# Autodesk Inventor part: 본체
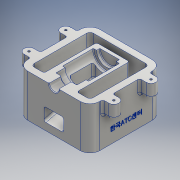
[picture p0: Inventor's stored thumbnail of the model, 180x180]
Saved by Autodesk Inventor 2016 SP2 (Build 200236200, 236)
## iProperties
Created: 2018-01
Part Number: 본체
Material: 알루미늄 6061
Document SubType Name: Modeling
Designer: Administrator
Density: 2.7 g/cm^3
Appearance: 알루미늄 - 평지
Mass: 988.682 g
Surface Area: 837.246 cm^2
Volume: 366.178 cm^3
Author: Administrator
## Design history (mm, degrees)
sketch "스케치1"
  geometry: L1 (-40, 55)-(40, 55); L2 (55, 40)-(55, -40); L3 (40, -55)-(-40, -55); L4 (-55, -40)-(-55, 40); L5 (-55, 55)-(55, -55); L6 (55, 55)-(-55, -55); L7 (40, 45)-(-40, 45); L8 (-45, 40)-(-45, -40); L9 (-40, -45)-(40, -45); L10 (45, -40)-(45, 40); A1 r 15 centre (-40, 40) between (-40, 55) and (-55, 40); A2 r 15 centre (40, 40) between (55, 40) and (40, 55); A3 r 15 centre (40, -40) between (40, -55) and (55, -40); A4 r 15 centre (-40, -40) between (-55, -40) and (-40, -55); A5 r 5 centre (-40, 40) between (-40, 45) and (-45, 40); A6 r 5 centre (40, 40) between (45, 40) and (40, 45); A7 r 5 centre (40, -40) between (40, -45) and (45, -40); A8 r 5 centre (-40, -40) between (-45, -40) and (-40, -45); 1 further point
  constraints: 20 end point, 16 point on circle, 16 tangent, 8 centre point, 8 point on line, 6 equal radius, 4 parallel, 2 midpoint, 2 perpendicular, 1 horizontal, 3 other
  dimensions: "d0" = 110 distance of L5.end L6.end; "d1" = 110 distance of L6.start L5.end; "d2" = 10 distance between parallel lines of L1 L7; "d3" = 15 radius of A1; "d4" = 5 radius of A5
extrude "돌출1" new body sketch "스케치1" distance "d5" = 65; taper "d6" = 0 deg
sketch "스케치2"
  geometry: L1 (-40, -55)-(40, -55) reference; L2 (-55, 40)-(-55, -40) reference; L3 (55, -40)-(55, 40) reference; L4 (-65, 35.5)-(-48.474, 35.5); L5 (-65, 20.5)-(-48.474, 20.5); L6 (-65, -20.5)-(-48.474, -20.5); L7 (-48.474, -20.5)-(-48.474, -35.5); L8 (-48.474, -35.5)-(-65, -35.5); L9 (64.286, -20.5)-(47.99, -20.5); L10 (47.99, -20.5)-(47.99, -35.5); L11 (47.99, -35.5)-(64.286, -35.5); L12 (65, 20.5)-(47.99, 20.5); L13 (47.99, 20.5)-(47.99, 35.5); L14 (47.99, 35.5)-(65, 35.5); L15 (-48.474, 20.5)-(-48.474, 35.5); A1 r 7.5 centre (-65, 28) between (-65, 35.5) and (-65, 20.5); A2 r 7.5 centre (-65, -28) between (-65, -20.5) and (-65, -35.5); A3 r 7.5 centre (65, 28) between (65, 20.5) and (65, 35.5); A4 r 7.5 centre (64.286, -28) between (64.286, -35.5) and (64.286, -20.5); 2 further points
  constraints: 24 end point, 8 point on circle, 7 point on line, 5 horizontal, 5 tangent, 4 centre point, 2 horizontal alignment, 2 perpendicular, 2 vertical, 1 midpoint, 1 vertical alignment
  dimensions: "d7" = 15 diameter of A1; "d8" = 15 diameter of A2; "d9" = 15 diameter of A3; "d10" = 15 diameter of A4; "d11" = 27 distance from line of A2.centre L1; "d12" = 56 distance of A1.centre A2.centre; "d13" = 10 distance from line of A1.centre L2; "d14" = 10 distance from line of A3.centre L3
extrude "돌출2" join sketch "스케치2" distance "d15" = 20; taper "d16" = 0 deg
sketch "스케치3"
  geometry: L1 (-55, -35.5)-(-55, -40) reference; L2 (-40, -55)-(40, -55) reference; L3 (55, -40)-(55, -35.5) reference; L4 (64.286, -35.5)-(55, -35.5) reference; L5 (55, -20.5)-(64.286, -20.5) reference; L6 (55, -20.5)-(55, 20.5) reference; L7 (55, 20.5)-(65, 20.5) reference; L8 (65, 35.5)-(55, 35.5) reference; L9 (55, 35.5)-(55, 40) reference; L10 (40, 55)-(-40, 55) reference; L11 (-55, 40)-(-55, 35.5) reference; L12 (-55, 35.5)-(-65, 35.5) reference; L13 (-65, 20.5)-(-55, 20.5) reference; L14 (-55, 20.5)-(-55, -20.5) reference; L15 (-55, -20.5)-(-65, -20.5) reference; L16 (-65, -35.5)-(-55, -35.5) reference; L17 (-40, 45)-(40, 45) reference; L18 (45, 40)-(45, -40) reference; L19 (40, -45)-(-40, -45) reference; L20 (-45, -40)-(-45, 40) reference; A1 r 15 centre (-40, -40) between (-55, -40) and (-40, -55) reference; A2 r 15 centre (40, -40) between (40, -55) and (55, -40) reference; A3 r 7.5 centre (64.286, -28) between (64.286, -35.5) and (64.286, -20.5) reference; A4 r 7.5 centre (65, 28) between (65, 20.5) and (65, 35.5) reference; A5 r 15 centre (40, 40) between (55, 40) and (40, 55) reference; A6 r 15 centre (-40, 40) between (-40, 55) and (-55, 40) reference; A7 r 7.5 centre (-65, 28) between (-65, 35.5) and (-65, 20.5) reference; A8 r 7.5 centre (-65, -28) between (-65, -20.5) and (-65, -35.5) reference; A9 r 5 centre (-40, 40) between (-40, 45) and (-45, 40) reference; A10 r 5 centre (40, 40) between (45, 40) and (40, 45) reference; A11 r 5 centre (40, -40) between (40, -45) and (45, -40) reference; A12 r 5 centre (-40, -40) between (-45, -40) and (-40, -45) reference; 5 further points
  constraints: 4 coincident
hole "구멍1" sketch "스케치3" at (-65, 28), (-65, -28), (64.286, -28), (65, 28) diameter "d17" = 3.242; stored, may be unused: countersink angle "d21" = 90 deg, drill point angle "d23" = 118 deg; dims "d18" = 9, "d19" = 4, "d20" = 2, "d22" = 11
sketch "스케치6"
  geometry: L1 (-51.166, 6.912)-(35, 30); L2 (35, 30)-(35, 65); L3 (-40, 65)-(40, 65) reference; L4 (-40, 65)-(-55, 65) reference; L5 (-51.166, 65)-(-51.166, 6.912); L6 (40, 0)-(-40, 0) reference; L7 (55, 0)-(55, 65) reference; 1 further point
  constraints: 6 end point, 2 point on line, 1 perpendicular, 1 vertical
  dimensions: "d27" = 105 deg angle of L5 L1; "d28" = 30 distance from line of L1.end L6; "d29" = 20 distance between parallel lines of L2 L7; "d30" = 86.16553 distance between parallel lines of L5 L2
extrude "돌출3" join sketch "스케치6" stored distance "d31" = 50; taper "d32" = 0 deg
sketch "스케치8"
  geometry: L1 (-55, 0)-(-55, 65) reference; L2 (-55, 57.5)-(-36, 57.5); L3 (-40, 0)-(-40, 65) reference; L4 (-22, 45)-(25, 45); L5 (-45, 65)-(35, 65) reference; L6 (-40, 65)-(-55, 65) reference; L7 (30, 65)-(-55, 65); L8 (-36, 57.5)-(-36, 49); L9 (-36, 49)-(-22, 49); L10 (-22, 49)-(-22, 45); L11 (25, 45)-(25, 50); L12 (25, 50)-(30, 50); L13 (20.5, 65)-(20.5, 45) reference; L14 (30, 50)-(30, 65); 2 further points
  constraints: 18 end point, 4 vertical, 2 horizontal, 2 perpendicular, 2 point on line, 1 collinear
  dimensions: "d34" = 15 diameter of L2 L7; "d35" = 32 diameter of L9 L7; "d37" = 40 diameter of L4 L7; "d38" = 30 diameter of L12 L7; "d39" = 19 distance between parallel lines of L1 L8; "d40" = 14 distance between parallel lines of L8 L10; "d41" = 47 distance between parallel lines of L10 L11; "d42" = 5 distance between parallel lines of L14 L11
revolve "회전1" sketch "스케치8" stored, may be unused: angle "d43" = 90 deg
sketch "스케치9"
  geometry: L1 (20, 31.157)-(20, 58.635); L2 (20, 58.635)-(-17, 58.635); L3 (-17, 58.635)-(-17, 41.48); L4 (-17, 41.48)-(-61.053, 29.676); L5 (20, 31.157)-(-61.053, 9.439); L6 (-61.053, 9.439)-(-61.053, 29.676); L7 (-55, 0)-(-55, 65) reference; L8 (35, 30)-(-45, 8.564) reference; L9 (-22, 45)-(25, 45) reference; 2 further points
  constraints: 12 end point, 2 parallel, 2 perpendicular, 1 midpoint, 1 vertical
  dimensions: "d44" = 5 distance from line of L8 L5.end; "d46" = 37 distance between parallel lines of L3 L1; "d48" = 13.63477 distance between parallel lines of L9 L2; "d49" = 75 distance between parallel lines of L1 L7; "d64" = 75 deg angle of L7 L4; "d65" = 6.05333 distance between parallel lines of L6 L7; "d66" = 19.54743 distance between parallel lines of L5 L4
extrude "돌출4" cut sketch "스케치9" stored distance "d51" = 30; taper "d52" = 0 deg
sketch "스케치10"
  geometry: 1 further point
node "작업 평면2"
sketch "스케치11"
  geometry: L1 (-40, 0)-(40, 0) reference; 2 further points
  constraints: 1 vertical alignment, 1 other
  dimensions: "d55" = 20 distance from line of point (0, 20) L1
feature "엠보싱1" sketch "스케치11" dims "d0" = 110, "d1" = 110, "d2" = 10, "d3" = 15, "d4" = 5, "d56" = 0.5, "d57" = 0
fillet "모깎기1" dims "d58" = 3, "d59" = 1
fillet "모깎기2" dims "d60" = 3
chamfer "모따기1" distance "d61" = 1; stored, may be unused: second distance "d62" = 2, angle "d63" = 45 deg
sketch "스케치12"
  geometry: 1 further point
fillet "모깎기3" dims "d67" = 3
node "솔리드1"
node "투영된 루프1"
